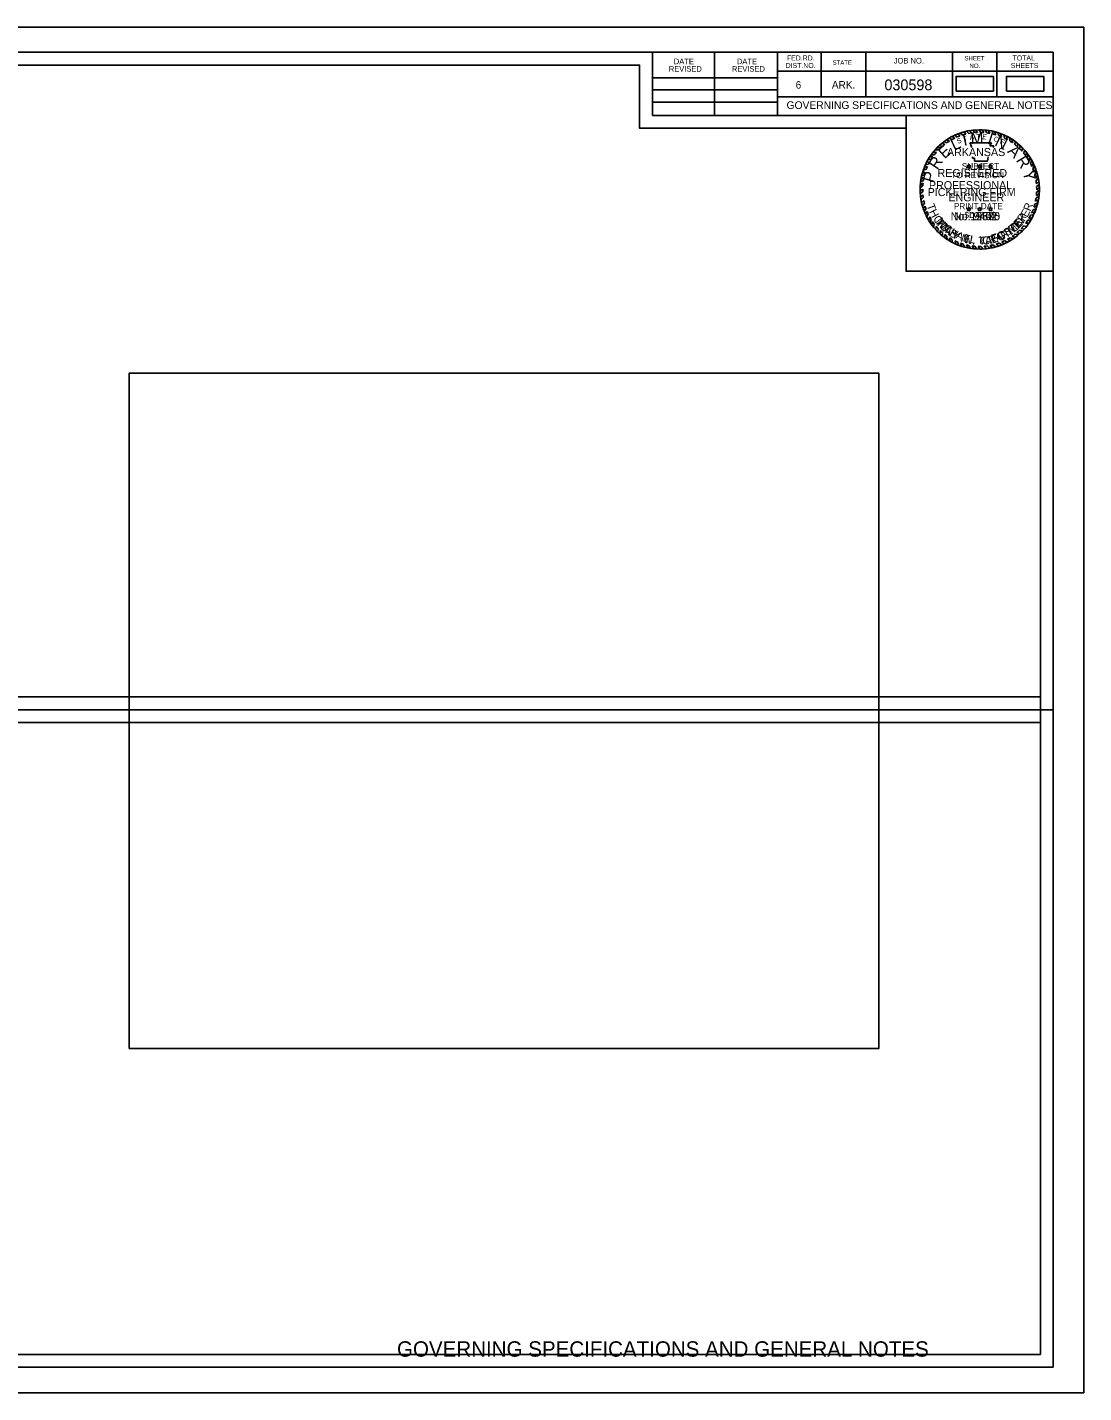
# Model space of a CAD drawing. Extents: x 1369940 to 1370273, y 380086 to 380299.
# Drawn here: x 1370108 to 1370273.1, y 380085.7 to 380299.1 of the extents above; entities that cross this region are included whole.
import ezdxf

# ---------------------------------------------------------------- set-up
doc = ezdxf.new("R2010")
doc.units = 0
for name, color, linetype in [('Default', 7, 'Continuous'), ('R_Border', 7, 'Continuous'), ('R_Border Notes', 7, 'Continuous'), ('R_Border Plan-Plan', 7, 'Continuous'), ('R_Border Title', 7, 'Continuous'), ('R_No Plot', 7, 'Continuous'), ('STAMP_PE_CRAFTON', 7, 'Continuous'), ('STAMP_PE_FOSTER', 7, 'Continuous'), ('STAMP_PE_SEAL-INFO', 7, 'Continuous'), ('STAMP_PE_TAEGTMEYER', 7, 'Continuous'), ('STAMP_PE_TXT', 7, 'Continuous'), ('STAMP_PRELIMINARY', 7, 'Continuous')]:
    doc.layers.add(name, color=color, linetype=linetype)

msp = doc.modelspace()

# ---------------------------------------------------------------- linework, layer by layer
at = {"layer": 'Default'}
for points in [[(1370253.11, 380289.09), (1370258.94, 380289.09), (1370258.94, 380291.4), (1370253.11, 380291.4)], [(1370260.98, 380289.09), (1370266.81, 380289.09), (1370266.81, 380291.4), (1370260.98, 380291.4)], [(1370123.88, 380139.54), (1370241.04, 380139.54), (1370241.04, 380245.03), (1370123.88, 380245.03)]]:
    msp.add_lwpolyline(points, close=True, dxfattribs=at)
at = {"layer": 'R_Border'}
for p, q in [((1369952.12, 380295.18), (1370268.3, 380295.18)), ((1370205.66, 380285.3), (1370205.66, 380295.18)), ((1370215.34, 380285.3), (1370215.34, 380295.18)), ((1370225.2, 380295.18), (1370225.2, 380285.3)), ((1370232.04, 380295.18), (1370232.04, 380288.24)), ((1370238.98, 380295.18), (1370238.98, 380288.24)), ((1370252.56, 380295.18), (1370252.56, 380288.24)), ((1370259.5, 380295.18), (1370259.5, 380288.24)), ((1370268.3, 380089.72), (1370268.3, 380295.18)), ((1370268.3, 380292.24), (1370225.2, 380292.24)), ((1370268.3, 380292.26), (1370268.3, 380292.26)), ((1370205.66, 380291.16), (1370225.2, 380291.16)), ((1370205.66, 380289.3), (1370225.2, 380289.3)), ((1370205.66, 380287.36), (1370225.2, 380287.36)), ((1370268.3, 380288.24), (1370225.2, 380288.24)), ((1370228.16, 380288.24), (1370268.3, 380288.24)), ((1370268.3, 380285.3), (1370205.66, 380285.3)), ((1370268.3, 380089.72), (1369952.12, 380089.72))]:
    msp.add_line(p, q, dxfattribs=at)
at = {"layer": 'R_Border Plan-Plan'}
msp.add_line((1369952.12, 380192.45), (1370268.3, 380192.45), dxfattribs=at)
at = {"layer": 'R_No Plot'}
for points in [[(1369939.71, 380299.08), (1370273.05, 380299.08), (1370273.05, 380085.74), (1369939.71, 380085.74)], [(1370266.3, 380194.45), (1369954.12, 380194.45), (1369954.12, 380293.18), (1370203.66, 380293.18), (1370203.66, 380283.3), (1370221.2, 380283.3), (1370245.3, 380283.3), (1370245.3, 380260.97), (1370266.3, 380260.97)], [(1369954.12, 380293.18), (1370203.66, 380293.18), (1370203.66, 380283.3), (1370221.2, 380283.3), (1370245.3, 380283.3), (1370245.3, 380260.97), (1370266.3, 380260.97), (1370266.3, 380091.72), (1369954.12, 380091.72)], [(1370245.3, 380285.3), (1370268.3, 380285.3), (1370268.3, 380260.97), (1370245.3, 380260.97)], [(1369954.12, 380190.45), (1370266.3, 380190.45), (1370266.3, 380091.72), (1369954.12, 380091.72)]]:
    msp.add_lwpolyline(points, close=True, dxfattribs=at)
at = {"layer": 'STAMP_PE_SEAL-INFO'}
for p, q in [((1370254.74, 380282.84), (1370255.09, 380282.5)), ((1370255.22, 380282.94), (1370255.52, 380282.57)), ((1370255.73, 380283.01), (1370256.02, 380282.63)), ((1370256.47, 380282.65), (1370256.16, 380283.05)), ((1370256.97, 380282.66), (1370256.69, 380283.07)), ((1370257.43, 380282.64), (1370257.17, 380283.06)), ((1370257.93, 380282.59), (1370257.64, 380283.03)), ((1370258.36, 380282.52), (1370258.1, 380282.98)), ((1370258.92, 380282.4), (1370258.75, 380282.86)), ((1370250.84, 380280.92), (1370251.37, 380280.82)), ((1370251.22, 380281.24), (1370251.67, 380281.04)), ((1370251.64, 380281.51), (1370252.08, 380281.31)), ((1370252.02, 380281.75), (1370252.46, 380281.53)), ((1370252.47, 380282.01), (1370252.93, 380281.78)), ((1370252.9, 380282.22), (1370253.29, 380281.94)), ((1370253.41, 380282.43), (1370253.7, 380282.11)), ((1370253.76, 380282.56), (1370254.14, 380282.25)), ((1370254.35, 380282.74), (1370254.64, 380282.39)), ((1370255.27, 380281.04), (1370258.62, 380281.04)), ((1370255.39, 380280.73), (1370255.27, 380281.04)), ((1370255.5, 380280.43), (1370255.39, 380280.73)), ((1370258.62, 380281.04), (1370258.39, 380280.55)), ((1370259.32, 380282.3), (1370259.16, 380282.77)), ((1370259.77, 380282.15), (1370259.63, 380282.63)), ((1370260.19, 380281.99), (1370260.05, 380282.49)), ((1370260.65, 380281.78), (1370260.55, 380282.28)), ((1370261.1, 380281.56), (1370261.01, 380282.06)), ((1370261.49, 380281.33), (1370261.45, 380281.83)), ((1370261.92, 380281.04), (1370261.89, 380281.56)), ((1370262.28, 380280.78), (1370262.32, 380281.26)), ((1370262.73, 380280.4), (1370262.75, 380280.93)), ((1370248.98, 380278.82), (1370249.49, 380278.86)), ((1370249.21, 380279.17), (1370249.72, 380279.16)), ((1370249.49, 380279.54), (1370250.04, 380279.56)), ((1370249.84, 380279.95), (1370250.36, 380279.91)), ((1370250.16, 380280.29), (1370250.7, 380280.25)), ((1370250.5, 380280.62), (1370250.95, 380280.48)), ((1370255.5, 380280.32), (1370255.5, 380280.43)), ((1370255.69, 380278.61), (1370255.67, 380278.83)), ((1370256.01, 380278.61), (1370255.69, 380278.61)), ((1370256.01, 380278.18), (1370256.01, 380278.61)), ((1370258.13, 380278.83), (1370258.05, 380278.52)), ((1370258.39, 380280.55), (1370259.02, 380280.55)), ((1370259.02, 380280.55), (1370258.88, 380280.32)), ((1370263.04, 380280.11), (1370263.11, 380280.61)), ((1370263.4, 380279.74), (1370263.47, 380280.26)), ((1370263.67, 380279.42), (1370263.81, 380279.89)), ((1370264, 380279), (1370264.13, 380279.5)), ((1370264.22, 380278.69), (1370264.39, 380279.15)), ((1370264.52, 380278.19), (1370264.71, 380278.68)), ((1370247.82, 380276.27), (1370248.3, 380276.44)), ((1370247.98, 380276.77), (1370248.46, 380276.91)), ((1370248.13, 380277.18), (1370248.63, 380277.32)), ((1370248.31, 380277.61), (1370248.82, 380277.71)), ((1370248.5, 380278), (1370249, 380278.06)), ((1370248.73, 380278.42), (1370249.22, 380278.44)), ((1370258.04, 380278.18), (1370256.01, 380278.18)), ((1370258.05, 380278.52), (1370258.04, 380278.18)), ((1370264.72, 380277.82), (1370264.95, 380278.27)), ((1370264.96, 380277.34), (1370265.18, 380277.83)), ((1370265.1, 380277), (1370265.36, 380277.44)), ((1370265.29, 380276.45), (1370265.56, 380276.93)), ((1370265.4, 380276.09), (1370265.69, 380276.54)), ((1370247.9, 380274.3), (1370247.48, 380274.04)), ((1370247.94, 380274.72), (1370247.5, 380274.44)), ((1370248, 380275.16), (1370247.55, 380274.93)), ((1370248.08, 380275.62), (1370247.62, 380275.37)), ((1370247.72, 380275.86), (1370248.19, 380276.05)), ((1370265.53, 380275.53), (1370265.85, 380275.98)), ((1370265.6, 380275.15), (1370265.95, 380275.5)), ((1370265.67, 380274.64), (1370266.04, 380274.98)), ((1370265.7, 380274.22), (1370266.09, 380274.52)), ((1370247.88, 380273.8), (1370247.48, 380273.47)), ((1370247.89, 380273.4), (1370247.5, 380273.07)), ((1370247.92, 380272.9), (1370247.55, 380272.54)), ((1370247.98, 380272.47), (1370247.62, 380272.1)), ((1370265.61, 380272.41), (1370266.05, 380272.63)), ((1370265.66, 380272.79), (1370266.09, 380273.05)), ((1370265.7, 380273.3), (1370266.12, 380273.58)), ((1370265.71, 380273.71), (1370266.12, 380274.03)), ((1370248.06, 380272.01), (1370247.72, 380271.64)), ((1370248.15, 380271.59), (1370247.84, 380271.18)), ((1370248.27, 380271.15), (1370247.98, 380270.73)), ((1370248.41, 380270.72), (1370248.13, 380270.31)), ((1370248.58, 380270.3), (1370248.32, 380269.87)), ((1370264.92, 380270.07), (1370265.4, 380270.16)), ((1370265.13, 380270.58), (1370265.61, 380270.71)), ((1370265.26, 380270.96), (1370265.75, 380271.16)), ((1370265.41, 380271.45), (1370265.88, 380271.66)), ((1370265.52, 380271.91), (1370265.97, 380272.1)), ((1370248.75, 380269.91), (1370248.52, 380269.45)), ((1370248.99, 380269.45), (1370248.8, 380268.96)), ((1370249.22, 380269.05), (1370249.04, 380268.58)), ((1370249.42, 380268.74), (1370249.31, 380268.19)), ((1370249.71, 380268.35), (1370249.6, 380267.82)), ((1370250.01, 380267.97), (1370249.92, 380267.45)), ((1370263.66, 380268.06), (1370264.12, 380267.98)), ((1370263.97, 380268.46), (1370264.48, 380268.46)), ((1370264.31, 380268.95), (1370264.79, 380268.94)), ((1370264.48, 380269.23), (1370264.98, 380269.29)), ((1370264.75, 380269.73), (1370265.24, 380269.8)), ((1370250.31, 380267.63), (1370250.25, 380267.11)), ((1370250.63, 380267.31), (1370250.6, 380266.78)), ((1370250.98, 380267), (1370250.98, 380266.47)), ((1370251.34, 380266.7), (1370251.36, 380266.18)), ((1370251.68, 380266.45), (1370251.71, 380265.93)), ((1370252.1, 380266.17), (1370252.16, 380265.66)), ((1370252.45, 380265.96), (1370252.55, 380265.45)), ((1370260.72, 380265.74), (1370261.21, 380265.53)), ((1370261.13, 380265.96), (1370261.55, 380265.72)), ((1370261.54, 380266.2), (1370261.99, 380266.01)), ((1370261.89, 380266.43), (1370262.33, 380266.24)), ((1370262.35, 380266.77), (1370262.82, 380266.63)), ((1370262.62, 380267), (1370263.09, 380266.87)), ((1370263.03, 380267.37), (1370263.47, 380267.23)), ((1370263.28, 380267.63), (1370263.76, 380267.54)), ((1370252.94, 380265.71), (1370253.09, 380265.19)), ((1370253.31, 380265.55), (1370253.48, 380265.03)), ((1370253.8, 380265.35), (1370254.01, 380264.85)), ((1370254.21, 380265.22), (1370254.44, 380264.73)), ((1370254.72, 380265.08), (1370254.93, 380264.61)), ((1370255.12, 380264.99), (1370255.36, 380264.54)), ((1370255.62, 380264.91), (1370255.86, 380264.47)), ((1370256.05, 380264.87), (1370256.33, 380264.44)), ((1370256.54, 380264.84), (1370256.84, 380264.42)), ((1370257, 380264.84), (1370257.34, 380264.44)), ((1370257.52, 380264.86), (1370257.84, 380264.48)), ((1370257.95, 380264.91), (1370258.33, 380264.55)), ((1370258.4, 380264.98), (1370258.79, 380264.64)), ((1370258.89, 380265.08), (1370259.27, 380264.76)), ((1370259.35, 380265.21), (1370259.77, 380264.91)), ((1370259.84, 380265.37), (1370260.29, 380265.1)), ((1370260.26, 380265.53), (1370260.69, 380265.27))]:
    msp.add_line(p, q, dxfattribs=at)
for radius, start, end in [(9.32, 99.7525, 102.7765), (9.32, 93.9381, 96.5517), (9.32, 87.7298, 90.6707), (9.32, 81.9732, 84.8236), (9.32, 75.3125, 77.9426), (9.32, 129.7326, 132.5376), (8.91, 127.5297, 130.9683), (9.32, 123.6199, 126.5906), (8.91, 121.9746, 125.11), (9.32, 117.6544, 120.8099), (8.91, 115.6869, 119.1583), (9.32, 111.3124, 114.7026), (8.91, 110.3086, 113.1659), (9.32, 105.2339, 109.0352), (8.91, 104.0352, 107.3615), (8.91, 98.258, 101.0329), (8.91, 92.1102, 95.0367), (8.91, 85.9628, 88.9097), (8.91, 79.9264, 82.696), (8.91, 73.5575, 76.2314), (9.32, 69.6061, 72.3058), (8.91, 67.6248, 70.504), (9.32, 63.1329, 66.2704), (8.91, 61.1558, 64.3784), (9.32, 56.9003, 60.0942), (8.91, 54.9238, 58.2702), (8.91, 48.3016, 52.0395), (9.32, 50.3492, 53.7159), (9.32, 147.0072, 149.899), (9.32, 141.6056, 144.4486), (8.91, 145.0197, 148.2104), (8.91, 139.301, 142.5873), (9.32, 135.4021, 138.3031), (8.91, 133.1331, 136.2562), (8.91, 42.2212, 45.5512), (9.32, 44.3405, 47.3929), (8.91, 36.135, 39.5311), (9.32, 38.1247, 41.2316), (8.91, 29.9032, 33.6645), (9.32, 31.9614, 35.4294), (9.32, 158.4077, 161.0701), (8.91, 162.4331, 165.0013), (9.32, 152.864, 155.5189), (8.91, 156.3402, 159.2319), (8.91, 151.0315, 153.573), (8.91, 23.7732, 27.2211), (9.32, 25.9391, 29.0125), (8.91, 17.6802, 21.4251), (9.32, 19.9538, 23.3141), (9.32, 13.8421, 17.4447), (9.32, 175.7409, 178.2066), (9.32, 170.0003, 172.6878), (9.32, 164.3068, 166.894), (8.91, 173.73, 176.4734), (8.91, 167.9048, 170.9039), (8.91, 11.5444, 15.2364), (8.91, 5.7599, 9.0606), (9.32, 7.5852, 10.8621), (9.32, 1.7215, 4.7268), (9.32, 181.7251, 184.1626), (9.32, 187.4204, 190.1927), (8.91, 179.6454, 182.2633), (8.91, 185.4539, 188.234), (8.91, 348.0778, 351.3435), (8.91, 353.8632, 357.1274), (8.91, 359.7329, 3.0639), (9.32, 349.8305, 353.0885), (9.32, 355.7156, 358.9569), (9.32, 193.0369, 195.9973), (9.32, 198.8967, 201.6281), (8.91, 191.2274, 193.9858), (8.91, 196.9675, 199.8353), (8.91, 202.7761, 205.4791), (8.91, 335.6038, 339.1858), (8.91, 341.777, 345.0925), (9.32, 337.3837, 340.9933), (9.32, 343.8925, 347.035), (9.32, 204.5479, 207.4328), (9.32, 210.8636, 213.6571), (8.91, 208.7883, 211.7934), (9.32, 216.6115, 219.491), (8.91, 214.1838, 217.2747), (8.91, 220.3909, 223.3056), (8.91, 316.6531, 320.3711), (9.32, 318.2846, 321.8043), (8.91, 323.5851, 327.4407), (8.91, 329.5549, 333.2076), (9.32, 325.4405, 328.9872), (9.32, 331.4037, 334.9332), (9.32, 222.48, 225.3801), (9.32, 228.3665, 231.348), (8.91, 226.2494, 229.2407), (8.91, 232.229, 234.9336), (9.32, 234.295, 236.9452), (8.91, 238.2223, 240.8353), (8.91, 292.8745, 296.1185), (8.91, 299.0768, 302.1724), (9.32, 300.621, 303.8703), (8.91, 304.823, 308.5143), (9.32, 306.3721, 310.208), (8.91, 310.7744, 314.3161), (9.32, 312.4518, 315.6633), (9.32, 240.1977, 242.8613), (8.91, 244.3204, 246.9486), (9.32, 246.576, 249.1558), (8.91, 250.3491, 253.1216), (9.32, 252.5967, 255.3252), (8.91, 256.505, 259.1192), (9.32, 258.4433, 261.1398), (8.91, 262.3783, 265.2012), (9.32, 264.1978, 267.1009), (8.91, 268.3215, 271.277), (9.32, 270.2548, 273.3361), (8.91, 274.6157, 277.4486), (9.32, 276.4239, 279.4357), (8.91, 280.3459, 283.5814), (9.32, 282.3199, 285.3702), (8.91, 286.6423, 289.9783), (9.32, 288.5709, 291.9733), (9.32, 294.6481, 298.2166)]:
    msp.add_arc((1370256.8, 380273.75), radius, start, end, dxfattribs=at)
at = {"layer": 'STAMP_PE_TXT'}
for p, q in [((1370254.98, 380277.32), (1370254.78, 380277.46)), ((1370254.78, 380277.46), (1370255.02, 380277.46)), ((1370254.9, 380277.09), (1370254.98, 380277.32)), ((1370255.1, 380277.23), (1370254.9, 380277.09)), ((1370255.02, 380277.46), (1370255.1, 380277.7)), ((1370255.1, 380277.7), (1370255.18, 380277.46)), ((1370255.3, 380277.09), (1370255.1, 380277.23)), ((1370255.18, 380277.46), (1370255.42, 380277.46)), ((1370255.42, 380277.46), (1370255.22, 380277.32)), ((1370255.22, 380277.32), (1370255.3, 380277.09)), ((1370256.68, 380277.32), (1370256.48, 380277.46)), ((1370256.48, 380277.46), (1370256.72, 380277.46)), ((1370256.6, 380277.09), (1370256.68, 380277.32)), ((1370256.8, 380277.23), (1370256.6, 380277.09)), ((1370256.72, 380277.46), (1370256.8, 380277.7)), ((1370256.8, 380277.7), (1370256.87, 380277.46)), ((1370257, 380277.09), (1370256.8, 380277.23)), ((1370256.87, 380277.46), (1370257.12, 380277.46)), ((1370257.12, 380277.46), (1370256.92, 380277.32)), ((1370256.92, 380277.32), (1370257, 380277.09)), ((1370258.37, 380277.32), (1370258.17, 380277.46)), ((1370258.17, 380277.46), (1370258.42, 380277.46)), ((1370258.3, 380277.09), (1370258.37, 380277.32)), ((1370258.5, 380277.23), (1370258.3, 380277.09)), ((1370258.42, 380277.46), (1370258.5, 380277.7)), ((1370258.5, 380277.7), (1370258.57, 380277.46)), ((1370258.69, 380277.09), (1370258.5, 380277.23)), ((1370258.57, 380277.46), (1370258.82, 380277.46)), ((1370258.82, 380277.46), (1370258.62, 380277.32)), ((1370258.62, 380277.32), (1370258.69, 380277.09)), ((1370254.98, 380270.61), (1370254.78, 380270.76)), ((1370254.78, 380270.76), (1370255.02, 380270.76)), ((1370254.9, 380270.38), (1370254.98, 380270.61)), ((1370255.1, 380270.52), (1370254.9, 380270.38)), ((1370255.02, 380270.76), (1370255.1, 380270.99)), ((1370255.1, 380270.99), (1370255.18, 380270.76)), ((1370255.3, 380270.38), (1370255.1, 380270.52)), ((1370255.18, 380270.76), (1370255.42, 380270.76)), ((1370255.42, 380270.76), (1370255.22, 380270.61)), ((1370255.22, 380270.61), (1370255.3, 380270.38)), ((1370256.68, 380270.61), (1370256.48, 380270.76)), ((1370256.48, 380270.76), (1370256.72, 380270.76)), ((1370256.6, 380270.38), (1370256.68, 380270.61)), ((1370256.8, 380270.52), (1370256.6, 380270.38)), ((1370256.72, 380270.76), (1370256.8, 380270.99)), ((1370256.8, 380270.99), (1370256.87, 380270.76)), ((1370257, 380270.38), (1370256.8, 380270.52)), ((1370256.87, 380270.76), (1370257.12, 380270.76)), ((1370257.12, 380270.76), (1370256.92, 380270.61)), ((1370256.92, 380270.61), (1370257, 380270.38)), ((1370258.37, 380270.61), (1370258.17, 380270.76)), ((1370258.17, 380270.76), (1370258.42, 380270.76)), ((1370258.3, 380270.38), (1370258.37, 380270.61)), ((1370258.5, 380270.52), (1370258.3, 380270.38)), ((1370258.42, 380270.76), (1370258.5, 380270.99)), ((1370258.5, 380270.99), (1370258.57, 380270.76)), ((1370258.69, 380270.38), (1370258.5, 380270.52)), ((1370258.57, 380270.76), (1370258.82, 380270.76)), ((1370258.82, 380270.76), (1370258.62, 380270.61)), ((1370258.62, 380270.61), (1370258.69, 380270.38))]:
    msp.add_line(p, q, dxfattribs=at)
at = {"layer": 'STAMP_PRELIMINARY'}
msp.add_circle((1370256.8, 380273.75), 9.32, dxfattribs=at)

# ---------------------------------------------------------------- texts
at = {"layer": 'R_Border'}
for s, height, p in [('DATE', 0.879, (1370209, 380293.32)), ('DATE', 0.879, (1370218.86, 380293.32)), ('DIST.NO.', 0.782, (1370226.48, 380292.72)), ('FED.RD.', 0.782, (1370226.68, 380293.9)), ('STATE', 0.684, (1370233.8, 380293.22)), ('JOB NO.', 0.879, (1370243.38, 380293.42)), ('SHEET', 0.684, (1370254.42, 380293.9)), ('SHEETS', 0.782, (1370261.66, 380292.72)), ('TOTAL', 0.782, (1370261.94, 380293.9)), ('REVISED', 0.879, (1370208.22, 380292.14)), ('REVISED', 0.879, (1370218.08, 380292.14)), ('NO.', 0.684, (1370255.2, 380292.72)), ('6', 1.17, (1370228.04, 380289.5)), ('ARK.', 1.172, (1370233.7, 380289.5))]:
    msp.add_text(s, height=height, dxfattribs=at).set_placement(p)
at = {"layer": 'R_Border Notes'}
for s, height, p in [('030598', 1.68, (1370241.91, 380289.25)), ('GOVERNING SPECIFICATIONS AND GENERAL NOTES', 1.2, (1370226.62, 380286.32))]:
    msp.add_text(s, height=height, dxfattribs=at).set_placement(p)
at = {"layer": 'R_Border Title'}
msp.add_text('GOVERNING SPECIFICATIONS AND GENERAL NOTES', height=2.4, dxfattribs=at).set_placement((1370165.74, 380091.37))
at = {"layer": 'STAMP_PE_CRAFTON'}
msp.add_text('No. 12370', height=1.25, dxfattribs=at).set_placement((1370252.26, 380268.94))
for s, rotation, p in [('T', 310.7442, (1370249.76, 380268.65)), ('O', 317.6422, (1370250.43, 380267.83)), ('N', 324.4537, (1370251.28, 380267.05)), ('T', 34.1136, (1370261.37, 380266.39)), ('O', 41.8391, (1370262.23, 380266.99)), ('N', 49.2411, (1370263.08, 380267.77)), ('Y', 331.1686, (1370252.31, 380266.33)), ('N', 347.4752, (1370254.36, 380265.42)), ('C', 6.0117, (1370257.27, 380265.09)), ('R', 14.8189, (1370258.37, 380265.2)), ('A', 20.5125, (1370259.48, 380265.5)), ('F', 28.7821, (1370260.46, 380265.88)), ('.', 356.8926, (1370255.59, 380265.14))]:
    msp.add_text(s, height=1.25, rotation=rotation, dxfattribs=at).set_placement(p)
at = {"layer": 'STAMP_PE_FOSTER'}
msp.add_text('No. 9402', height=1.25, dxfattribs=at).set_placement((1370252.78, 380268.94))
for s, rotation, p in [('M', 308.339, (1370249.91, 380268.77)), ('I', 314.1842, (1370250.71, 380267.83)), ('C', 319.8733, (1370251.07, 380267.48)), ('T', 39.4194, (1370261.94, 380266.99)), ('E', 46.9613, (1370262.8, 380267.74)), ('R', 54.5031, (1370263.52, 380268.56)), ('H', 327.7235, (1370252, 380266.74)), ('A', 335.7276, (1370252.98, 380266.16)), ('E', 343.5779, (1370254.11, 380265.69)), ('L', 350.8115, (1370255.17, 380265.41)), ('L', 1.2666, (1370256.71, 380265.26)), ('F', 15.8691, (1370258.83, 380265.5)), ('O', 23.719, (1370259.88, 380265.83)), ('S', 31.7234, (1370260.99, 380266.36)), ('.', 6.8035, (1370257.76, 380265.31))]:
    msp.add_text(s, height=1.2, rotation=rotation, dxfattribs=at).set_placement(p)
at = {"layer": 'STAMP_PE_TAEGTMEYER'}
for s, rotation, p in [('T', 289.646, (1370248.49, 380271.26)), ('H', 296.7339, (1370248.85, 380270.27)), ('E', 63.0984, (1370264.24, 380269.28)), ('R', 69.57, (1370264.74, 380270.26)), ('O', 303.7708, (1370249.45, 380269.17)), ('M', 314.2033, (1370250.1, 380268.21)), ('A', 321.0594, (1370251.06, 380267.25)), ('M', 39.3, (1370261.8, 380266.65)), ('E', 46.8094, (1370262.84, 380267.52)), ('Y', 53.9986, (1370263.58, 380268.34)), ('S', 327.8239, (1370251.89, 380266.61)), ('N', 344.2727, (1370253.78, 380265.6)), ('T', 3.0061, (1370256.66, 380265.07)), ('A', 8.9826, (1370257.71, 380265.12)), ('E', 17.6836, (1370258.75, 380265.28)), ('G', 23.3052, (1370259.8, 380265.61)), ('T', 31.466, (1370260.9, 380266.1)), ('.', 350.6464, (1370255, 380265.27))]:
    msp.add_text(s, height=1.25, rotation=rotation, dxfattribs=at).set_placement(p)
msp.add_text('No. 19605', height=1.25, dxfattribs=at).set_placement((1370252.26, 380268.94))
at = {"layer": 'STAMP_PE_TXT'}
for s, rotation, p in [('S', 23.5541, (1370253.4, 380280.85)), ('T', 16.311, (1370254.32, 380281.22)), ('A', 9.0679, (1370255.28, 380281.48)), ('T', 1.8248, (1370256.27, 380281.61)), ('E', 355.2002, (1370257.18, 380281.61)), ('O', 342.2506, (1370258.91, 380281.34)), ('F', 335.0075, (1370259.87, 380281))]:
    msp.add_text(s, height=0.781, rotation=rotation, dxfattribs=at).set_placement(p)
for s, p in [('ARKANSAS', (1370251.69, 380278.96)), ('REGISTERED', (1370250.21, 380275.69)), ('PROFESSIONAL', (1370248.87, 380273.79)), ('ENGINEER', (1370251.91, 380271.89))]:
    msp.add_text(s, height=1.25, dxfattribs=at).set_placement(p)
at = {"layer": 'STAMP_PRELIMINARY'}
for s, rotation, p in [('E', 42.3578, (1370251.32, 380278.44)), ('L', 25.513, (1370252.81, 380279.77)), ('I', 12.5248, (1370254.34, 380280.53)), ('M', 3.1074, (1370255.43, 380280.84)), ('I', 342.3164, (1370257.9, 380280.91)), ('N', 333.9382, (1370259.01, 380280.64)), ('R', 56.2292, (1370250.17, 380276.71)), ('A', 315.6579, (1370261.04, 380279.61)), ('R', 301.3831, (1370262.41, 380278.3)), ('P', 73.913, (1370249.62, 380274.69)), ('Y', 283.2593, (1370263.5, 380276.51))]:
    msp.add_text(s, height=1.8, rotation=rotation, dxfattribs=at).set_placement(p)
for s, height, p in [('TO REVISION', 0.96, (1370252.33, 380275.51)), ('SUBJECT', 0.96, (1370254, 380276.9)), ('PICKERING FIRM', 1.25, (1370248.67, 380272.71)), ('PRINT DATE', 0.96, (1370252.76, 380270.66)), ('$DATE$', 0.96, (1370254.43, 380269.28))]:
    msp.add_text(s, height=height, dxfattribs=at).set_placement(p)

doc.saveas('drawing.dxf')
